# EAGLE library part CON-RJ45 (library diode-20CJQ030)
Various RJ45 Surface Mount Jacks Kycon Molex Please send any comments to: messi@users.sourceforge.net
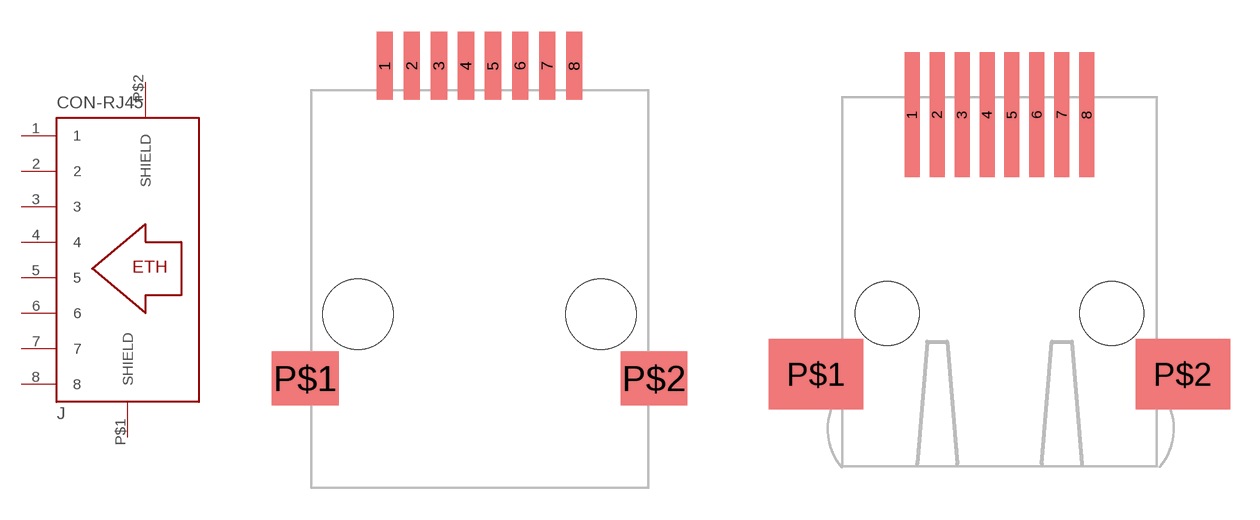
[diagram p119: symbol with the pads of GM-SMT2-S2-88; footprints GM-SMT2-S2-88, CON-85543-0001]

Designator prefix J

## CON-RJ45-1  [GM-SMT2-S2-88]
1  1  pas
2  2  pas
3  3  pas
4  4  pas
5  5  pas
6  6  pas
7  7  pas
8  8  pas
P$1  SHIELD  pas
P$2  SHIELD  pas

## CON-RJ45-2  [CON-85543-0001]
Pads as for GM-SMT2-S2-88

## Footprint GM-SMT2-S2-88 (pad centres in mm)
Kycon's GM-SMT2-S2-88 GM-SMT2 Series Surface Mount Modular Jack Features: 0.45" Height Low Profile Design Suitable for PC Add-On Board Applications Available in 4, 6, 8, and 10 Position Housings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
smd 0.76 x 3.185: 1 -4.445,11.665; 2 -3.175,11.665; 3 -1.905,11.665; 4 -0.635,11.665; 5 0.635,11.665; 6 1.905,11.665; 7 3.175,11.665; 8 4.445,11.665
smd 3.12 x 2.54: P$1 -8.175,-3.005; P$2 8.175,-3.005
hole 3.3 at -5.7,0
hole 3.3 at 5.7,0

## Footprint CON-85543-0001 (pad centres in mm)
Molex 85543-0001 High speed right angle fully shielded modular jack (8-circuit) RJ45 Connector
smd 0.762 x 6.35: 1 -4.445,17.907; 2 -3.175,17.907; 3 -1.905,17.907; 4 -0.635,17.907; 5 0.635,17.907; 6 1.905,17.907; 7 3.175,17.907; 8 4.445,17.907
smd 4.8 x 3.6: P$1 -9.327,4.7; P$2 9.327,4.7
hole 3.251 at -5.715,7.798
hole 3.251 at 5.715,7.798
